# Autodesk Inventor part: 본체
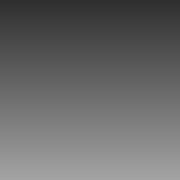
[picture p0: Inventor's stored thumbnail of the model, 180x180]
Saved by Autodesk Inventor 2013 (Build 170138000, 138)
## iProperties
Created: 2016-08
Part Number: 본체
Material: 일반
Document SubType Name: Modeling
Designer: Administrator
Density: 1 g/cm^3
Author: Administrator
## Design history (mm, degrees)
